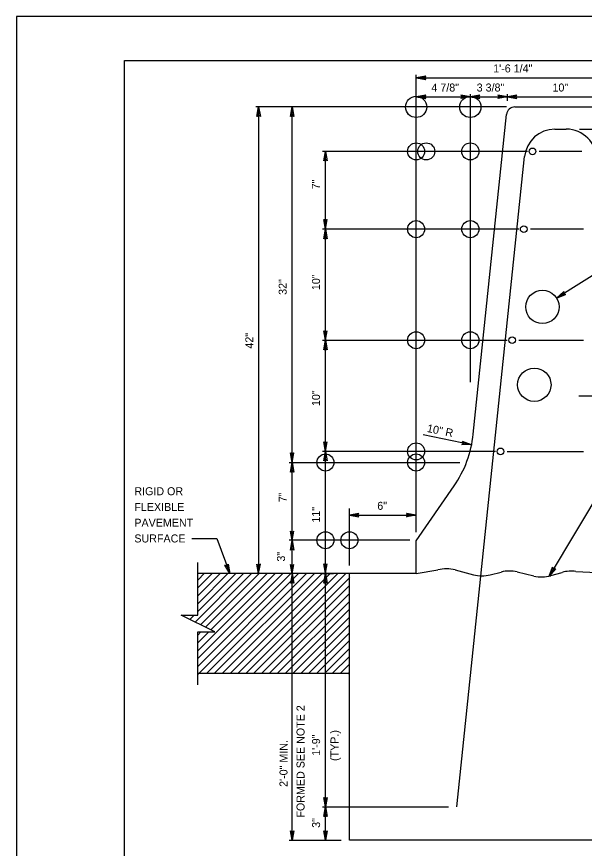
# Model space of a CAD drawing. Extents: x -27.4 to -18.9, y -4.2 to 6.8.
# Drawn here: x -27.42 to -23.16, y 0.57 to 6.81 of the extents above; entities that cross this region are included whole.
import ezdxf

# ---------------------------------------------------------------- set-up
doc = ezdxf.new("R2010")
doc.units = 0
for name, color, linetype in [('ANNO-WOUT', 7, 'Continuous'), ('BORD-LINE', 7, 'Continuous'), ('DETL-DIMS', 7, 'Continuous'), ('Level 1', 7, 'Continuous'), ('Level 10', 7, 'Continuous'), ('Level 12', 7, 'Continuous'), ('Level 6', 7, 'Continuous'), ('SECT-GRND_P', 7, 'Continuous'), ('SUBS-FOOT_P', 7, 'Continuous'), ('SUPR-PARA_P', 7, 'Continuous'), ('SUPR-RFRC', 7, 'Continuous'), ('USER-CLIP', 7, 'Continuous')]:
    doc.layers.add(name, color=color, linetype=linetype)

msp = doc.modelspace()

# ---------------------------------------------------------------- linework, layer by layer
at = {"layer": 'ANNO-WOUT'}
for centre, radius in [((-24.4207, 6.132), 0.0795), ((-24.0144, 6.132), 0.0795), ((-24.4207, 5.7987), 0.0639), ((-24.3447, 5.7987), 0.0639), ((-24.0144, 5.7987), 0.0639), ((-24.4207, 5.2153), 0.0639), ((-24.0144, 5.2153), 0.0639), ((-24.4207, 4.382), 0.0639), ((-24.0144, 4.382), 0.0639), ((-24.4207, 3.5486), 0.0639), ((-25.1005, 3.4653), 0.0639), ((-24.4207, 3.4653), 0.0639), ((-25.1005, 2.882), 0.0639), ((-24.9207, 2.882), 0.0639)]:
    msp.add_circle(centre, radius, dxfattribs=at)
at = {"layer": 'BORD-LINE'}
msp.add_lwpolyline([(-26.6066, 6.4791), (-19.2324, 6.4791), (-19.2324, -3.874), (-26.6066, -3.874)], close=True, dxfattribs=at)
at = {"layer": 'DETL-DIMS'}
for p, q in [((-24.4207, 6.3507), (-24.3492, 6.3632)), ((-24.3492, 6.3632), (-24.3627, 6.3507)), ((-24.4207, 6.3507), (-24.3492, 6.338)), ((-24.3627, 6.3507), (-24.3492, 6.338)), ((-24.4207, 6.2075), (-24.3492, 6.22)), ((-24.4207, 6.2075), (-24.3492, 6.1948)), ((-24.3492, 6.22), (-24.3627, 6.2075)), ((-24.3627, 6.2075), (-24.3492, 6.1948)), ((-24.0144, 6.2075), (-24.0859, 6.22)), ((-24.0859, 6.22), (-24.0724, 6.2075)), ((-24.0144, 6.2075), (-24.0859, 6.1948)), ((-24.0724, 6.2075), (-24.0859, 6.1948)), ((-24.0145, 6.2075), (-23.943, 6.22)), ((-24.0145, 6.2075), (-23.943, 6.1948)), ((-23.943, 6.22), (-23.9565, 6.2075)), ((-23.9565, 6.2075), (-23.943, 6.1948)), ((-23.7366, 6.2075), (-23.8081, 6.22)), ((-23.8081, 6.22), (-23.7946, 6.2075)), ((-23.7366, 6.2075), (-23.8081, 6.1948)), ((-23.7946, 6.2075), (-23.8081, 6.1948)), ((-23.7367, 6.2075), (-23.6652, 6.22)), ((-23.7367, 6.2075), (-23.6652, 6.1948)), ((-23.6652, 6.22), (-23.6787, 6.2075)), ((-23.6787, 6.2075), (-23.6652, 6.1948)), ((-25.6012, 6.132), (-25.6137, 6.0605)), ((-25.6012, 6.132), (-25.5885, 6.0605)), ((-25.3512, 6.132), (-25.3637, 6.0605)), ((-25.3512, 6.132), (-25.3385, 6.0605)), ((-25.6137, 6.0605), (-25.6012, 6.074)), ((-25.6012, 6.074), (-25.5885, 6.0605)), ((-25.3637, 6.0605), (-25.3512, 6.074)), ((-25.3512, 6.074), (-25.3385, 6.0605)), ((-25.1005, 5.7987), (-25.113, 5.7272)), ((-25.113, 5.7272), (-25.1005, 5.7407)), ((-25.1005, 5.7987), (-25.0878, 5.7272)), ((-25.1005, 5.7407), (-25.0878, 5.7272)), ((-25.1005, 5.2153), (-25.113, 5.2868)), ((-25.113, 5.2868), (-25.1005, 5.2733)), ((-25.1005, 5.2153), (-25.0878, 5.2868)), ((-25.1005, 5.2733), (-25.0878, 5.2868)), ((-25.1005, 5.2153), (-25.113, 5.1438)), ((-25.1005, 5.2153), (-25.0878, 5.1438)), ((-25.113, 5.1438), (-25.1005, 5.1573)), ((-25.1005, 5.1573), (-25.0878, 5.1438)), ((-23.3681, 4.6984), (-23.3142, 4.7472)), ((-23.3189, 4.7292), (-23.3142, 4.7472)), ((-23.3681, 4.6984), (-23.3009, 4.7258)), ((-23.3009, 4.7258), (-23.3189, 4.7292)), ((-25.1005, 4.382), (-25.113, 4.4535)), ((-25.113, 4.4535), (-25.1005, 4.44)), ((-25.1005, 4.382), (-25.0878, 4.4535)), ((-25.1005, 4.44), (-25.0878, 4.4535)), ((-25.1005, 4.382), (-25.113, 4.3105)), ((-25.1005, 4.382), (-25.0878, 4.3105)), ((-25.113, 4.3105), (-25.1005, 4.324)), ((-25.1005, 4.324), (-25.0878, 4.3105)), ((-25.1005, 3.5486), (-25.113, 3.6201)), ((-25.113, 3.6201), (-25.1005, 3.6066)), ((-25.1005, 3.5486), (-25.0878, 3.6202)), ((-25.1005, 3.6066), (-25.0878, 3.6202)), ((-24.0047, 3.5971), (-24.0722, 3.6237)), ((-24.0722, 3.6237), (-24.0615, 3.6087)), ((-24.0615, 3.6087), (-24.0773, 3.599)), ((-24.0047, 3.5971), (-24.0773, 3.599)), ((-25.3512, 3.4653), (-25.3637, 3.5368)), ((-25.3637, 3.5368), (-25.3512, 3.5233)), ((-25.3512, 3.4653), (-25.3385, 3.5368)), ((-25.3512, 3.5233), (-25.3385, 3.5368)), ((-25.1005, 3.5486), (-25.113, 3.4771)), ((-25.1005, 3.5486), (-25.0878, 3.4771)), ((-25.3512, 3.4653), (-25.3637, 3.3938)), ((-25.3512, 3.4653), (-25.3385, 3.3938)), ((-25.113, 3.4771), (-25.1005, 3.4906)), ((-25.1005, 3.4906), (-25.0878, 3.4771)), ((-25.3637, 3.3938), (-25.3512, 3.4073)), ((-25.3512, 3.4073), (-25.3385, 3.3938)), ((-24.9207, 3.0705), (-24.8492, 3.083)), ((-24.9207, 3.0705), (-24.8492, 3.0578)), ((-24.8492, 3.083), (-24.8627, 3.0705)), ((-24.8627, 3.0705), (-24.8492, 3.0578)), ((-24.4206, 3.0705), (-24.4922, 3.0578)), ((-24.4786, 3.0705), (-24.4922, 3.0578)), ((-24.4206, 3.0705), (-24.4921, 3.083)), ((-24.4921, 3.083), (-24.4786, 3.0705)), ((-25.3512, 2.8792), (-25.3637, 2.9507)), ((-25.3637, 2.9507), (-25.3512, 2.9372)), ((-25.3512, 2.8792), (-25.3385, 2.9507)), ((-25.3512, 2.9372), (-25.3385, 2.9507)), ((-25.3512, 2.8792), (-25.3637, 2.8077)), ((-25.3512, 2.8792), (-25.3385, 2.8077)), ((-25.3637, 2.8077), (-25.3512, 2.8212)), ((-25.3512, 2.8212), (-25.3385, 2.8077)), ((-25.8171, 2.632), (-25.8542, 2.6945)), ((-25.8375, 2.6863), (-25.8542, 2.6945)), ((-25.8306, 2.7033), (-25.8375, 2.6863)), ((-25.8171, 2.632), (-25.8306, 2.7033)), ((-25.6012, 2.632), (-25.6137, 2.7035)), ((-25.6137, 2.7035), (-25.6012, 2.69)), ((-25.6012, 2.632), (-25.5885, 2.7035)), ((-25.6012, 2.69), (-25.5885, 2.7035)), ((-25.3512, 2.6292), (-25.3637, 2.7007)), ((-25.3637, 2.7007), (-25.3512, 2.6872)), ((-25.3512, 2.6292), (-25.3385, 2.7007)), ((-25.3512, 2.6872), (-25.3385, 2.7007)), ((-25.1005, 2.6348), (-25.113, 2.7063)), ((-25.113, 2.7063), (-25.1005, 2.6928)), ((-25.1005, 2.6348), (-25.0878, 2.7064)), ((-25.1005, 2.6928), (-25.0878, 2.7064)), ((-25.3512, 2.632), (-25.3638, 2.5605)), ((-25.3512, 2.632), (-25.3386, 2.5605)), ((-25.1005, 2.632), (-25.113, 2.5605)), ((-25.1005, 2.632), (-25.0878, 2.5605)), ((-23.4242, 2.6133), (-23.3984, 2.6812)), ((-23.4242, 2.6133), (-23.3767, 2.6682)), ((-23.3944, 2.6631), (-23.3984, 2.6812)), ((-23.3767, 2.6682), (-23.3944, 2.6631)), ((-25.3512, 2.574), (-25.3638, 2.5605)), ((-25.3386, 2.5605), (-25.3512, 2.574)), ((-25.113, 2.5605), (-25.1005, 2.574)), ((-25.1005, 2.574), (-25.0878, 2.5605)), ((-25.1005, 0.882), (-25.1132, 0.9535)), ((-25.1005, 0.94), (-25.1132, 0.9535)), ((-25.1005, 0.882), (-25.088, 0.9535)), ((-25.088, 0.9535), (-25.1005, 0.94)), ((-25.1005, 0.882), (-25.113, 0.8105)), ((-25.1005, 0.882), (-25.0878, 0.8105)), ((-25.113, 0.8105), (-25.1005, 0.824)), ((-25.1005, 0.824), (-25.0878, 0.8105)), ((-25.3512, 0.632), (-25.3638, 0.7035)), ((-25.3512, 0.69), (-25.3638, 0.7035)), ((-25.3512, 0.632), (-25.3386, 0.7035)), ((-25.3386, 0.7035), (-25.3512, 0.69)), ((-25.1005, 0.632), (-25.1132, 0.7035)), ((-25.1005, 0.69), (-25.1132, 0.7035)), ((-25.1005, 0.632), (-25.088, 0.7035)), ((-25.088, 0.7035), (-25.1005, 0.69))]:
    msp.add_line(p, q, dxfattribs=at)
for points in [[(-24.3492, 6.3632), (-24.4207, 6.3507), (-24.3492, 6.338), (-24.3627, 6.3507)], [(-24.3492, 6.22), (-24.4207, 6.2075), (-24.3492, 6.1948), (-24.3627, 6.2075)], [(-24.0859, 6.22), (-24.0144, 6.2075), (-24.0859, 6.1948), (-24.0724, 6.2075)], [(-23.943, 6.22), (-24.0145, 6.2075), (-23.943, 6.1948), (-23.9565, 6.2075)], [(-23.8081, 6.22), (-23.7366, 6.2075), (-23.8081, 6.1948), (-23.7946, 6.2075)], [(-23.6652, 6.22), (-23.7367, 6.2075), (-23.6652, 6.1948), (-23.6787, 6.2075)], [(-25.6137, 6.0605), (-25.6012, 6.132), (-25.5885, 6.0605), (-25.6012, 6.074)], [(-25.3637, 6.0605), (-25.3512, 6.132), (-25.3385, 6.0605), (-25.3512, 6.074)], [(-25.113, 5.7272), (-25.1005, 5.7987), (-25.0878, 5.7272), (-25.1005, 5.7407)], [(-25.113, 5.2868), (-25.1005, 5.2153), (-25.0878, 5.2868), (-25.1005, 5.2733)], [(-25.113, 5.1438), (-25.1005, 5.2153), (-25.0878, 5.1438), (-25.1005, 5.1573)], [(-23.3009, 4.7258), (-23.3681, 4.6984), (-23.3142, 4.7472), (-23.3189, 4.7292)], [(-25.113, 4.4535), (-25.1005, 4.382), (-25.0878, 4.4535), (-25.1005, 4.44)], [(-25.113, 4.3105), (-25.1005, 4.382), (-25.0878, 4.3105), (-25.1005, 4.324)], [(-25.113, 3.6201), (-25.1005, 3.5486), (-25.0878, 3.6202), (-25.1005, 3.6066)], [(-24.0722, 3.6237), (-24.0047, 3.5971), (-24.0773, 3.599), (-24.0615, 3.6087)], [(-25.3637, 3.5368), (-25.3512, 3.4653), (-25.3385, 3.5368), (-25.3512, 3.5233)], [(-25.113, 3.4771), (-25.1005, 3.5486), (-25.0878, 3.4771), (-25.1005, 3.4906)], [(-25.3637, 3.3938), (-25.3512, 3.4653), (-25.3385, 3.3938), (-25.3512, 3.4073)], [(-24.8492, 3.083), (-24.9207, 3.0705), (-24.8492, 3.0578), (-24.8627, 3.0705)], [(-24.4921, 3.083), (-24.4206, 3.0705), (-24.4922, 3.0578), (-24.4786, 3.0705)], [(-25.3637, 2.9507), (-25.3512, 2.8792), (-25.3385, 2.9507), (-25.3512, 2.9372)], [(-25.3637, 2.8077), (-25.3512, 2.8792), (-25.3385, 2.8077), (-25.3512, 2.8212)], [(-25.8306, 2.7033), (-25.8171, 2.632), (-25.8542, 2.6945), (-25.8375, 2.6863)], [(-25.6137, 2.7035), (-25.6012, 2.632), (-25.5885, 2.7035), (-25.6012, 2.69)], [(-25.3637, 2.7007), (-25.3512, 2.6292), (-25.3385, 2.7007), (-25.3512, 2.6872)], [(-25.113, 2.7063), (-25.1005, 2.6348), (-25.0878, 2.7064), (-25.1005, 2.6928)], [(-25.3386, 2.5605), (-25.3512, 2.632), (-25.3638, 2.5605), (-25.3512, 2.574)], [(-25.113, 2.5605), (-25.1005, 2.632), (-25.0878, 2.5605), (-25.1005, 2.574)], [(-23.3767, 2.6682), (-23.4242, 2.6133), (-23.3984, 2.6812), (-23.3944, 2.6631)], [(-25.088, 0.9535), (-25.1005, 0.882), (-25.1132, 0.9535), (-25.1005, 0.94)], [(-25.113, 0.8105), (-25.1005, 0.882), (-25.0878, 0.8105), (-25.1005, 0.824)], [(-25.3386, 0.7035), (-25.3512, 0.632), (-25.3638, 0.7035), (-25.3512, 0.69)], [(-25.088, 0.7035), (-25.1005, 0.632), (-25.1132, 0.7035), (-25.1005, 0.69)]]:
    msp.add_lwpolyline(points, close=True, dxfattribs=at)
at = {"layer": 'Level 1'}
for p, q in [((-26.0575, 2.3201), (-26.0575, 2.7153)), ((-24.9207, 1.882), (-24.9207, 2.632)), ((-24.9207, 1.882), (-24.9207, 2.632)), ((-25.929, 2.1947), (-26.1828, 2.3201)), ((-26.1828, 2.3201), (-26.0575, 2.3201)), ((-26.0575, 1.7987), (-26.0575, 2.1947)), ((-26.0575, 2.1947), (-25.929, 2.1947)), ((-24.9207, 1.882), (-26.0552, 1.882))]:
    msp.add_line(p, q, dxfattribs=at)
at = {"layer": 'Level 10'}
for p, q in [((-24.4207, 2.942), (-24.4207, 6.3715)), ((-24.4207, 6.3507), (-22.8998, 6.3507)), ((-24.4207, 6.2075), (-24.0144, 6.2075)), ((-24.0144, 4.0686), (-24.0144, 6.2283)), ((-24.0144, 6.2075), (-23.7366, 6.2075)), ((-23.7366, 6.1777), (-23.7366, 6.2283)), ((-23.7366, 6.2075), (-22.8998, 6.2075)), ((-23.7425, 6.132), (-25.622, 6.132)), ((-25.6012, 6.132), (-25.6012, 2.632)), ((-25.3512, 3.4653), (-25.3512, 6.132)), ((-23.1957, 5.9653), (-22.5748, 5.9653)), ((-23.5853, 5.7987), (-25.122, 5.7987)), ((-25.1005, 5.2153), (-25.1005, 5.7987)), ((-23.1778, 5.7987), (-23.4978, 5.7987)), ((-23.6518, 5.2153), (-25.122, 5.2153)), ((-25.1005, 4.382), (-25.1005, 5.2153)), ((-23.1665, 5.2153), (-23.5643, 5.2153)), ((-22.6858, 5.1263), (-23.3681, 4.6984)), ((-25.122, 4.382), (-23.7386, 4.382)), ((-25.1005, 3.5486), (-25.1005, 4.382)), ((-23.6511, 4.382), (-23.1665, 4.382)), ((-23.2017, 3.9653), (-23.0665, 3.9653)), ((-22.7813, 3.6866), (-23.4246, 2.6127)), ((-24.0047, 3.5971), (-24.3685, 3.6715)), ((-23.8254, 3.5486), (-25.122, 3.5486)), ((-25.1005, 2.632), (-25.1005, 3.5486)), ((-23.7379, 3.5486), (-23.1665, 3.5486)), ((-25.372, 3.4653), (-24.0932, 3.4653)), ((-25.3512, 2.8792), (-25.3512, 3.4653)), ((-24.9207, 2.692), (-24.9207, 3.1205)), ((-24.9207, 3.0705), (-24.4207, 3.0705)), ((-26.103, 2.8957), (-25.916, 2.8957)), ((-26.0797, 2.8957), (-25.916, 2.8957)), ((-25.916, 2.8957), (-25.8171, 2.632)), ((-24.4682, 2.882), (-25.372, 2.882)), ((-25.3512, 2.632), (-25.3512, 2.8792)), ((-25.3512, 0.632), (-25.3512, 2.632)), ((-25.1237, 2.632), (-25.0403, 2.632)), ((-25.1005, 0.882), (-25.1005, 2.632)), ((-24.9832, 1.882), (-25.4718, 1.882)), ((-25.122, 0.882), (-24.1785, 0.882)), ((-25.1005, 0.632), (-25.1005, 0.882)), ((-25.3726, 0.632), (-24.9832, 0.632))]:
    msp.add_line(p, q, dxfattribs=at)
at = {"layer": 'Level 6'}
for p, q in [((-26.0779, 2.2682), (-25.7141, 2.632)), ((-26.0575, 2.0529), (-25.4784, 2.632)), ((-26.0575, 1.994), (-25.4195, 2.632)), ((-26.0575, 2.3475), (-25.773, 2.632)), ((-26.0552, 2.4088), (-25.8319, 2.632)), ((-26.0552, 2.4677), (-25.8908, 2.632)), ((-26.0552, 2.5266), (-25.9498, 2.632)), ((-26.0552, 2.5855), (-26.0087, 2.632)), ((-26.0552, 1.8784), (-25.3016, 2.632)), ((-26.0552, 1.9374), (-25.3605, 2.632)), ((-26.0384, 2.2487), (-25.6551, 2.632)), ((-25.999, 2.2293), (-25.5962, 2.632)), ((-25.9927, 1.882), (-25.2427, 2.632)), ((-25.9595, 2.2098), (-25.5373, 2.632)), ((-25.9337, 1.882), (-25.1837, 2.632)), ((-25.8748, 1.882), (-25.1248, 2.632)), ((-25.8159, 1.882), (-25.0659, 2.632)), ((-25.757, 1.882), (-25.007, 2.632)), ((-25.698, 1.882), (-24.948, 2.632)), ((-25.6391, 1.882), (-24.9186, 2.6026)), ((-25.5802, 1.882), (-24.9207, 2.5415)), ((-25.5213, 1.882), (-24.9207, 2.4826)), ((-25.4623, 1.882), (-24.9207, 2.4237)), ((-26.1173, 2.2877), (-26.0849, 2.3201)), ((-25.4034, 1.882), (-24.9207, 2.3648)), ((-25.3445, 1.882), (-24.9207, 2.3058)), ((-25.2856, 1.882), (-24.9207, 2.2469)), ((-26.0575, 2.1118), (-25.9747, 2.1947)), ((-26.0575, 2.1708), (-26.0336, 2.1947)), ((-25.2266, 1.882), (-24.9207, 2.188)), ((-25.1677, 1.882), (-24.9207, 2.1291)), ((-25.1088, 1.882), (-24.9207, 2.0701)), ((-25.0499, 1.882), (-24.9207, 2.0112)), ((-24.9909, 1.882), (-24.9207, 1.9523)), ((-24.932, 1.882), (-24.9207, 1.8933))]:
    msp.add_line(p, q, dxfattribs=at)
at = {"layer": 'SECT-GRND_P'}
msp.add_line((-24.9207, 2.632), (-26.0552, 2.632), dxfattribs=at)
at = {"layer": 'SUBS-FOOT_P'}
for p, q in [((-24.9207, 0.632), (-24.9207, 2.632)), ((-24.4207, 2.632), (-24.2571, 2.6593)), ((-23.2225, 2.648), (-22.8998, 2.632)), ((-22.588, 0.632), (-24.9207, 0.632))]:
    msp.add_line(p, q, dxfattribs=at)
for points in [[(-24.4207, 2.632), (-24.9207, 2.632)], [(-24.1277, 2.6596), (-23.9908, 2.6233)], [(-23.8651, 2.6226), (-23.7834, 2.6434)], [(-23.663, 2.6441), (-23.5386, 2.614)], [(-23.4113, 2.6165), (-23.3257, 2.6409)]]:
    msp.add_lwpolyline(points, dxfattribs=at)
for centre, start, end in [((-24.1918, 2.418), 75.12718, 105.12455), ((-23.9267, 2.8649), 255.12718, 284.25594), ((-23.7218, 2.4011), 76.39951, 104.25594), ((-23.2572, 2.4004), 82.02465, 105.89103), ((-23.4798, 2.8569), 256.39951, 285.89103)]:
    msp.add_arc(centre, 0.25, start, end, dxfattribs=at)
at = {"layer": 'SUPR-PARA_P'}
for p, q in [((-23.6803, 6.132), (-22.9613, 6.132)), ((-23.9923, 3.6777), (-23.7425, 6.076)), ((-24.4207, 2.8784), (-24.1359, 3.2898)), ((-24.4207, 2.632), (-24.4207, 2.8784))]:
    msp.add_line(p, q, dxfattribs=at)
for centre in [(-23.474, 4.632), (-23.5347, 4.0487)]:
    msp.add_circle(centre, 0.125, dxfattribs=at)
for centre, radius, start, end in [((-23.6803, 6.0695), 0.0625, 90, 174.05314), ((-24.8212, 3.764), 0.8333, 325.31123, 354.05314)]:
    msp.add_arc(centre, radius, start, end, dxfattribs=at)
at = {"layer": 'SUPR-RFRC'}
for p, q in [((-23.3799, 5.9653), (-23.2957, 5.9653)), ((-24.116, 0.882), (-23.6078, 5.7599))]:
    msp.add_line(p, q, dxfattribs=at)
for centre in [(-23.5478, 5.7987), (-23.6143, 5.2153), (-23.7011, 4.382), (-23.7879, 3.5486)]:
    msp.add_circle(centre, 0.025, dxfattribs=at)
for centre, start, end in [((-23.3799, 5.7362), 90, 174.05314), ((-23.2957, 5.7362), 0, 90)]:
    msp.add_arc(centre, 0.2292, start, end, dxfattribs=at)
at = {"layer": 'USER-CLIP'}
msp.add_lwpolyline([(-18.9155, 6.8091), (-27.4155, 6.8091), (-27.4155, -4.1909), (-18.9155, -4.1909)], close=True, dxfattribs=at)

# ---------------------------------------------------------------- texts
at = {"layer": 'Level 12'}
for s, p in [('1\'-6 1/4"', (-23.8431, 6.3907)), ('4 7/8"', (-24.3062, 6.2475)), ('3 3/8"', (-23.9668, 6.2475)), ('10"', (-23.3986, 6.2475)), ('RIGID OR', (-26.5331, 3.2196)), ('RIGID OR', (-26.5331, 3.2196)), ('FLEXIBLE', (-26.5331, 3.1016)), ('FLEXIBLE', (-26.5331, 3.1016)), ('6"', (-24.712, 3.1104)), ('PAVEMENT', (-26.5331, 2.9836)), ('PAVEMENT', (-26.5331, 2.9836)), ('SURFACE', (-26.5331, 2.8656)), ('SURFACE', (-26.5331, 2.8656))]:
    msp.add_text(s, height=0.06001, dxfattribs=at).set_placement(p)
for s, height, rotation, p in [('7"', 0.06001, 90, (-25.1417, 5.5136)), ('10"', 0.06001, 90, (-25.1417, 4.7579)), ('32"', 0.06001, 90, (-25.3912, 4.7225)), ('42"', 0.06001, 90, (-25.6411, 4.3194)), ('10"', 0.06001, 90, (-25.1417, 3.8885)), ('10" R', 0.06001, 348.45194, (-24.3433, 3.6949)), ('7"', 0.06001, 90, (-25.3912, 3.1678)), ('11"', 0.06001, 90, (-25.1417, 3.0142)), ('3"', 0.06001, 90, (-25.4037, 2.7219)), ('FORMED SEE NOTE 2', 0.060009, 90, (-25.2573, 0.802)), ('(TYP.)', 0.06001, 90, (-25.0027, 1.2267)), ('2\'-0" MIN.', 0.06001, 90, (-25.385, 1.0322)), ('1\'-9"', 0.06001, 90, (-25.1407, 1.2653)), ('3"', 0.06001, 90, (-25.1407, 0.7253))]:
    msp.add_text(s, height=height, rotation=rotation, dxfattribs=at).set_placement(p)

doc.saveas('drawing.dxf')
